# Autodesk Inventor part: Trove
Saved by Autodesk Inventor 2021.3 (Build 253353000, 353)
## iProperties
Created: 2022-08
Part Number: Trove
Material: Generic
Document SubType Name: Modeling
Designer: Administrator
Density: 1 g/cm^3
Appearance: Default
Title: Trove v3
Author: Administrator
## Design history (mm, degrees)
feature "Trove" [Body]
feature "Socket Body" [Body]
feature "Shade Ring" [Body]
feature "Shade Ring +Collar" [Body]
feature "Socket" [Body]
feature "Body1"
feature "Metal Strain Relief" [Body]
feature "Fabric Cord (1)" [Body]
feature "Stem (Threaded)" [Body]
feature "Cap (Threaded)" [Body]
feature "5M Set Screw" [Body]
feature "T9-Bulb" [Body]
body "Solid1"
body "Solid2"
body "Solid3"
body "Solid4"
body "Solid5"
body "Solid6"
body "Solid7"
body "Solid8"
body "Solid9"
body "Solid10"
body "Solid11"
body "Solid12"
